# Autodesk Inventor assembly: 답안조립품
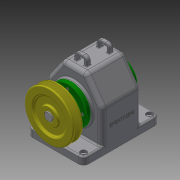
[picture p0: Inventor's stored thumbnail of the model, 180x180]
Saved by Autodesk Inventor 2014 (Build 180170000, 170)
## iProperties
Created: 2016-12
Part Number: 답안조립품
Document SubType Name: Assembly
Designer: owner
Author: owner
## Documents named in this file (15)
- C:\Users\owner\Desktop\461207V1019\답안조립품.iam
- C:\Users\owner\Desktop\461207V1019\본체.ipt
- C:\Users\owner\Desktop\461207V1019\키 - 6 x 6 x 22.ipt
- C:\Users\owner\Desktop\461207V1019\키 - 5 x 5 x 18.ipt
- C:\Users\owner\Desktop\461207V1019\축.ipt
- C:\Users\owner\Desktop\461207V1019\오일씰 28 40 8.ipt
- C:\Users\owner\Desktop\461207V1019\앞커버.ipt
- C:\Users\owner\Desktop\461207V1019\스퍼기어.ipt
- C:\Users\owner\Desktop\461207V1019\부시.ipt
- C:\Users\owner\Desktop\461207V1019\볼트 M3 x 10.ipt
- C:\Users\owner\Desktop\461207V1019\볼트 M3 x 8.ipt
- C:\Users\owner\Desktop\461207V1019\베어링 6203.ipt
- C:\Users\owner\Desktop\461207V1019\멈춤나사 - M4x10.ipt
- C:\Users\owner\Desktop\461207V1019\뒤커버.ipt
- C:\Users\owner\Desktop\461207V1019\V-벨트풀리.ipt
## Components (9 placed, 3 different names)
1. V-벨트풀리:1
2. ISO 4762 M3 x 10:1 — 각도:1
3. ISO 4762 M3 x 10:2
4. ISO 4762 M3 x 10:3
5. ISO 4762 M3 x 10:4
6. ISO 4762 M3 x 8:1 — 각도:2
7. ISO 4762 M3 x 8:2
8. ISO 4762 M3 x 8:3
9. ISO 4762 M3 x 8:4
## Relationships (2: Angle 2)
- 각도:1 [Angle]: ISO 4762 M3 x 10:1
- 각도:2 [Angle]: ISO 4762 M3 x 8:1
